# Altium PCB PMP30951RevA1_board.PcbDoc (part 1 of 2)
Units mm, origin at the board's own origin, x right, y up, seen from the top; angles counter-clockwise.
Board outline 87.63 x 58.42 mm, 2 copper layers (Top Layer, Bottom Layer), stack 1.575 mm thick; 82 components, 35 nets, 177 pads, 49 vias.
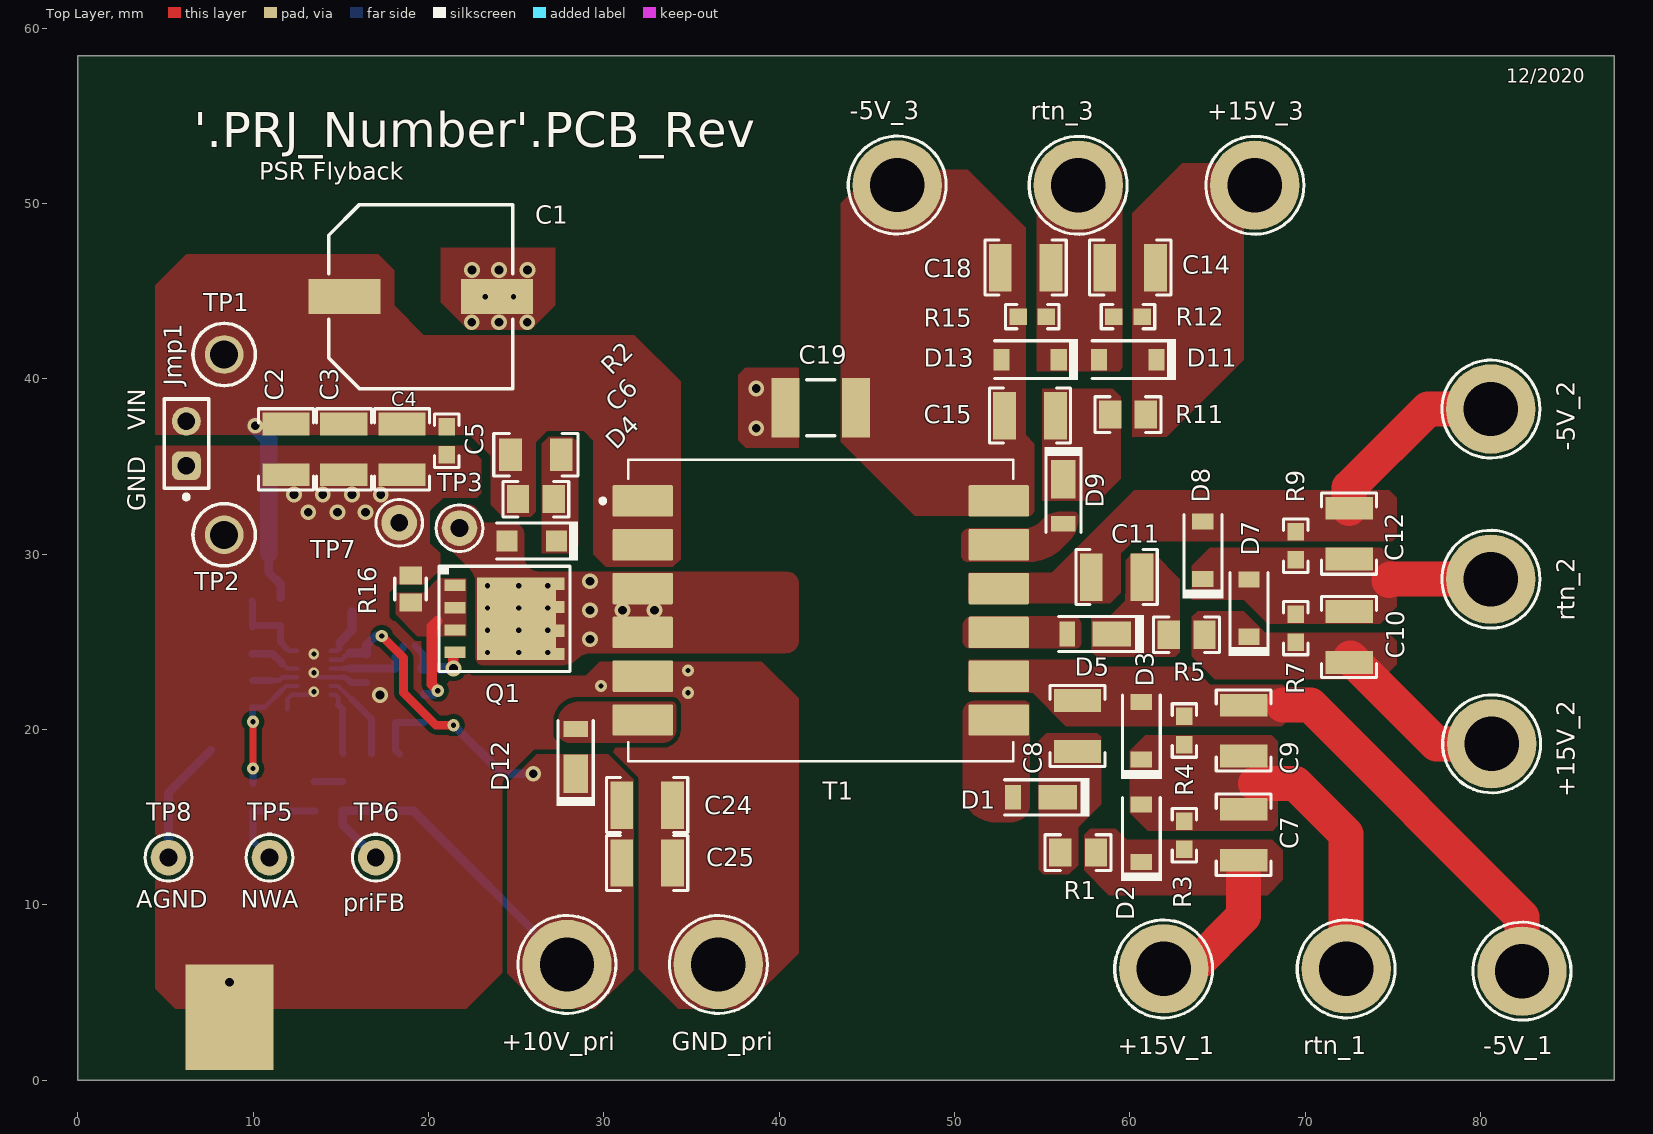
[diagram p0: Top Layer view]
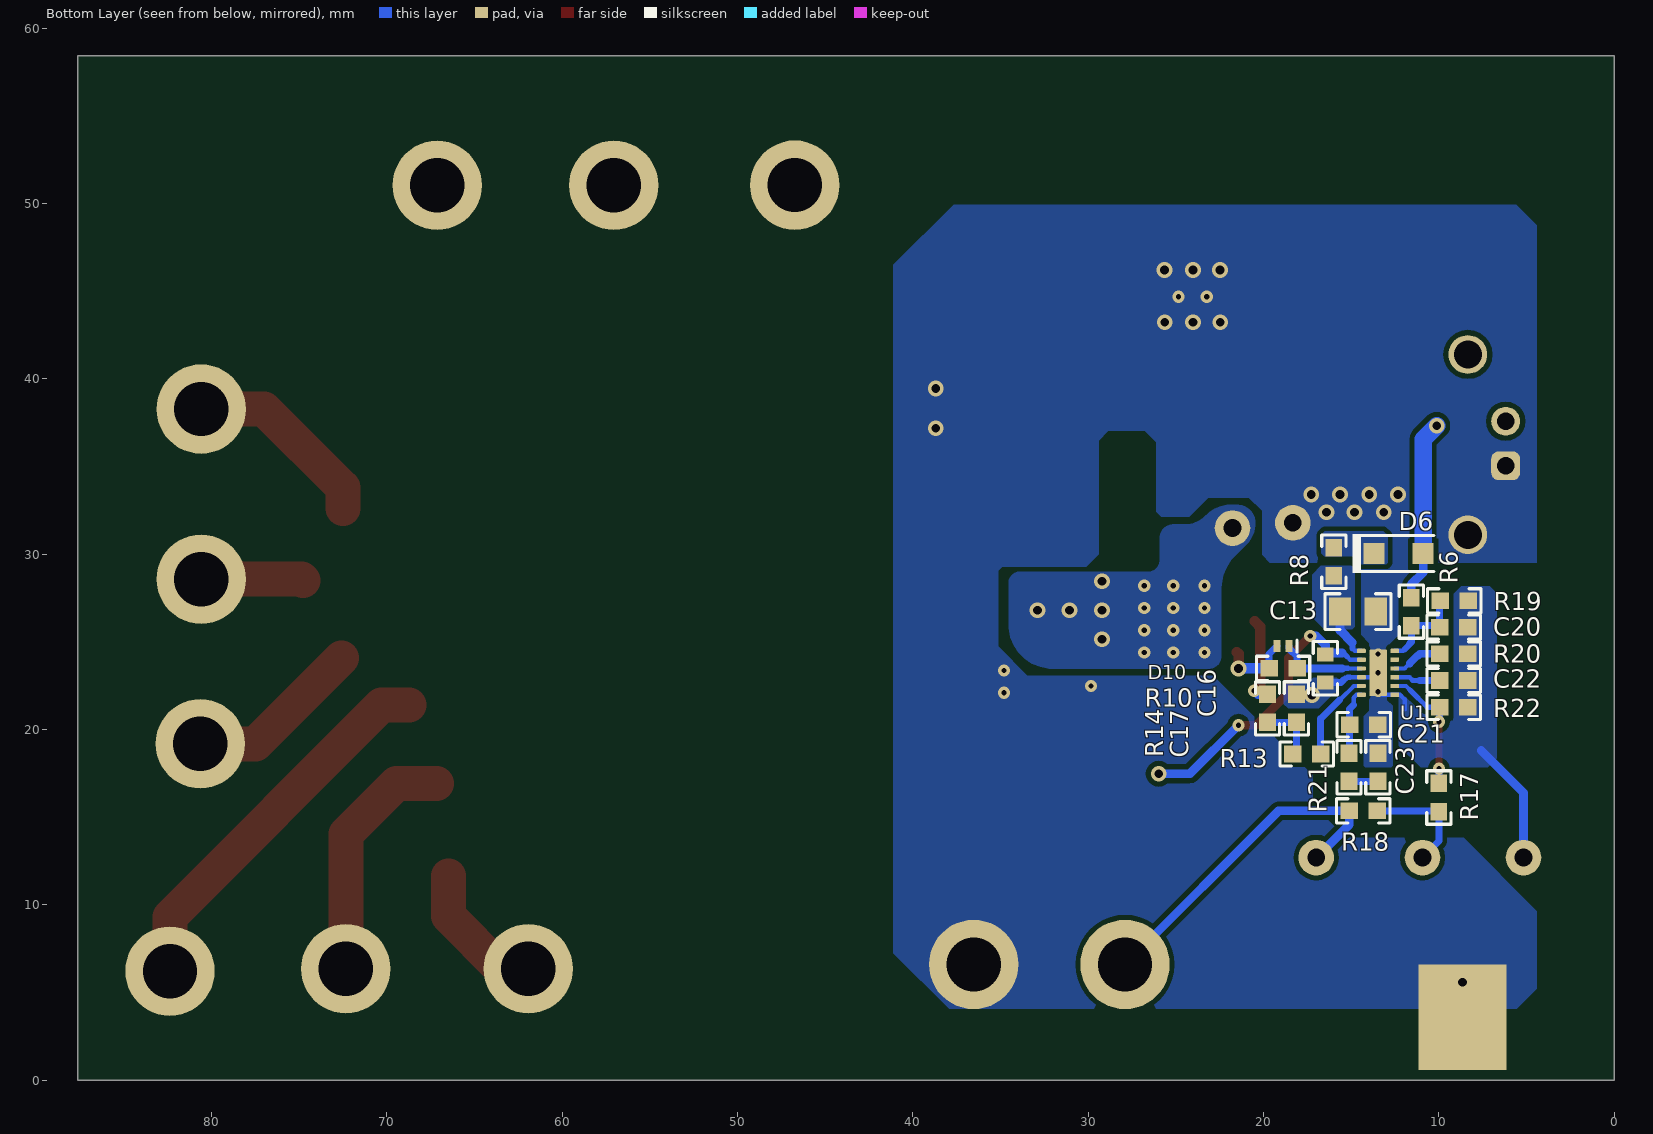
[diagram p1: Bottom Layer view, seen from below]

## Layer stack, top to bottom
Top Solder: solder mask 0.0102, Solder Resist, Dk 3.5
Top Layer: signal copper 0.0356
Dielectric1: core 1.5037, FR-4, Dk 4.8
Bottom Layer: signal copper 0.0356
Bottom Solder: solder mask 0.0102, Solder Resist, Dk 3.5

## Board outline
0,0 87.63,0 87.63,58.42 0,58.42

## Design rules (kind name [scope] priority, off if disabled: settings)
AcuteAngle [All] p1: minimum=4.50000000000000E+0001 checktracksonly=FALSE
AssemblyTestPointUsage [All] p1: valid=2
BoardOutlineClearance BoardOutlineClearance_MountingHoles [OnCopper and InComponentClass('Mounting Holes')] p1: gap=1 ignorepadtopadclearanceinfootprint=FALSE
BoardOutlineClearance BoardOutlineClearance_Poly [OnCopper and IsPoly] p2: gap=0.635 ignorepadtopadclearanceinfootprint=FALSE
BoardOutlineClearance [OnCopper and Not InComponentClass('Logo') and not InComponentClass('FiducialMark') and not InRegion(1000,500,4000,800) and not InPoly] p3: gap=1.905 ignorepadtopadclearanceinfootprint=FALSE
Clearance Clearance_Keepouts [((IsTrack Or IsArc) And Not InPoly) And IsFree and IsKeepOut vs ((IsTrack Or IsArc) And Not InPoly) And IsFree and IsKeepOut] p1: gap=0 ignorepadtopadclearanceinfootprint=FALSE
Clearance Clearance_Poly [InPolygon] p2: gap=0.28 ignorepadtopadclearanceinfootprint=TRUE
Clearance Clearance_FiducialMark [IsKeepOut and InComponentClass('FiducialMark') vs IsPad and InComponentClass('FiducialMark')] p3: gap=0 ignorepadtopadclearanceinfootprint=FALSE
Clearance [All] p4: gap=0.2 ignorepadtopadclearanceinfootprint=TRUE
ComponentClearance ComponentClearance_MountingHoles_FiducialMarks [InComponentClass('Mounting Holes') vs InComponentClass('FiducialMark')] p1: gap=1.27 collisioncheckmode=3 verticalgap=0.254 showdistances=FALSE
ComponentClearance ComponentClearance_Shunt [InComponentClass('Header') vs InComponentClass('Shunt')] p2: gap=0 collisioncheckmode=3 verticalgap=0 showdistances=FALSE
ComponentClearance ComponentClearance_Logo [InComponentClass('Logo')] p3: gap=1.27 collisioncheckmode=3 verticalgap=0.254 showdistances=FALSE
ComponentClearance ComponentClearance_ScrewToNut [(HasFootprint('NY PMS 440 0025 PH')) vs (HasFootprint('Keystone_1902C'))] p4: gap=0.127 collisioncheckmode=3 verticalgap=0.254 showdistances=FALSE
ComponentClearance ComponentClearance_MountingHoles [InComponentClass('Mounting Holes')] p5: gap=6.35 collisioncheckmode=3 verticalgap=2540 showdistances=FALSE
ComponentClearance ComponentClearance_SmallPassives [HasFootprint('0201*') or HasFootprint('0402*') or HasFootprint('0508') or HasFootprint('0603*') or HasFootprint('0612') or HasFootprint('0805*') or HasFootprint('0815*') or HasFootprint('0830*') or HasFootprint('1206*') or HasFootprint('1210*') or HasFootprint('1808*') or HasFootprint('1812*') or HasFootprint('1825*') or HasFootprint('2010*') or HasFootprint('2220*') or HasFootprint('2225*') or HasFootprint('2512*') or HasFootprint('2728*') or HasFootprint('3518*') or HasFootprint('X1-DFN1006-2') vs HasFootprint('0201*') or HasFootprint('0402*') or HasFootprint('0508') or HasFootprint('0603*') or HasFootprint('0612') or HasFootprint('0805*') or HasFootprint('0815*') or HasFootprint('0830*') or HasFootprint('1206*') or HasFootprint('1210*') or HasFootprint('1808*') or HasFootprint('1812*') or HasFootprint('1825*') or HasFootprint('2010*') or HasFootprint('2220*') or HasFootprint('2225*') or HasFootprint('2512*') or HasFootprint('2728*') or HasFootprint('3518*') or HasFootprint('X1-DFN1006-2')] p6: gap=0.38 collisioncheckmode=3 verticalgap=0.254 showdistances=FALSE
ComponentClearance ComponentClearance_THtoSMT [IsThruComponent vs IsSMTComponent] p7: gap=1.016 collisioncheckmode=3 verticalgap=0.762 showdistances=FALSE
ComponentClearance ComponentClearance_THtoTH [IsThruComponent vs IsThruComponent] p8: gap=0.762 collisioncheckmode=3 verticalgap=0.762 showdistances=FALSE
ComponentClearance [All] p9: gap=0.762 collisioncheckmode=3 verticalgap=0.254 showdistances=FALSE
DiffPairsRouting [All] p1: maxlimit=2.54 minlimit=0.254 mostfreqgap=0.254 toplayer_minwidth=0.381 toplayer_maxwidth=0.381 toplayer_prefwidth=0.381 bottomlayer_minwidth=0.381 bottomlayer_maxwidth=0.381 bottomlayer_prefwidth=0.381 maxuncoupledlength=25.4
FabricationTestPointUsage TestPointUsage [All] p1: valid=2 allowmultiple=FALSE
FabricationTestpoint Testpoint [All] p1: side=3 testpointundercomponent=TRUE minsize=1.016 maxsize=2.54 preferedsize=1.524 minholesize=0 maxholesize=1.016 preferedholesize=0.813 testpointgrid=0.025 allowsidetop=TRUE allowsidebottom=TRUE usegrid=TRUE gridtolerance=0
FanoutControl Fanout_LCC [IsLCC] p1: bgadir=Out bgaviamode=Centered fanoutstyle=Auto fanoutdirection=Alternating viagrid=0.025 // Fanout_LCC (Default Rule)
FanoutControl Fanout_BGA [IsBGA] p2: bgadir=Out bgaviamode=Centered fanoutstyle=Auto fanoutdirection=Alternating viagrid=0.025 // Fanout_BGA (Default Rule)
FanoutControl Fanout_Default [All] p4: bgadir=Out bgaviamode=Centered fanoutstyle=Auto fanoutdirection=Alternating viagrid=0.025 // Fanout_Default (Default Rule)
FanoutControl Fanout_Small [(CompPinCount < 5)] p5: bgadir=Out bgaviamode=Centered fanoutstyle=Auto fanoutdirection=OutThenIn viagrid=0.025 // Fanout_Small (Default Rule)
HoleSize [All] p1: absolutevalues=TRUE maxlimit=6.375 minlimit=0.3 maxpercent=80.000 minpercent=20.000
MinimumAnnularRing MinimumAnnularRing_ThermalPadVias [IsVia and InAnyComponent] p1: minimumring=0.15
MinimumAnnularRing [All] p2: minimumring=0.2
MinimumSolderMaskSliver MinimumSolderMaskSliver_Logo [InComponentClass('Logo') vs InComponentClass('Logo')] p1: minsoldermaskwidth=0.018
MinimumSolderMaskSliver [All] p2: minsoldermaskwidth=0.1
PlaneConnect [All] p1: planeconnectstyle=Relief reliefexpansion=0.254 reliefentries=4 reliefconductorwidth=0.254 reliefairgap=0.254
PolygonConnect PolygonConnect_TP8 [All vs InComponent('TP8')] p1: connectstyle=NoConnect reliefconductorwidth=0.254 reliefentries=4 polygonreliefangle="90 Angle" airgapwidth=0.254
PolygonConnect [All] p2: connectstyle=Direct reliefconductorwidth=0.254 reliefentries=4 polygonreliefangle="90 Angle" airgapwidth=0.254
RoutingVias ThermalPadVias [IsVia and InAnyComponent] p1: holewidth=0.2 width=0.5 viastyle="Through Hole" minholewidth=0.2 minwidth=0.5 maxholewidth=0.33 maxwidth=0.6
RoutingVias [All] p2: holewidth=0.5 width=0.9 viastyle="Through Hole" minholewidth=0.3 minwidth=0.6 maxholewidth=1.016 maxwidth=1.651
SilkToBoardRegionClearance [Not ((IsComment or IsDesignator) And (Hide <> 'False')) and not InRegion(1000,500,4000,800)] p1:
SilkToSilkClearance SilkToSilkClearance_Pb-FreeLogo [(HasFootprint('Pb-Free_Overlay_Medium') OR HasFootprint('Pb-Free_Overlay_Small')) vs (HasFootprint('Pb-Free_Overlay_Medium') OR HasFootprint('Pb-Free_Overlay_Small'))] p1: silktosilkclearance=0
SilkToSilkClearance [All] p2: silktosilkclearance=0.1
SilkToSolderMaskClearance SilkToComponentPadClearance [(IsPad or IsFill or IsRegion) and InAnycomponent] p1: minsilkscreentomaskgap=0.127 clearancetoexposedcopper=TRUE
SilkToSolderMaskClearance "Silk to Solder Mask Opening" [All] p2: minsilkscreentomaskgap=0.1 clearancetoexposedcopper=FALSE
SolderMaskExpansion [All] p1: expansion=0.05 istentingtop=FALSE
UnRoutedNet [All] p1: checkbadconnections=TRUE
Width [All] p1: maxlimit=2.54 minlimit=0.152 preferedwidth=0.254 checkconnectedcopper=TRUE
14 further rules are at their usual default settings.

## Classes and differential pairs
net class T1_Nets: GND Net-5V_1_1 Net-5V_2_1 Net-5V_3_1 NetD1_2 NetD5_2 NetD9_2 NetT?_7 NetT?_8 NetT?_9 NetT?_10 NetT?_11 NetT?_12 SW-aux SW_primary VIN
net class U1_Nets: 10Vaux GND NetC13_1 NetC20_1 NetC21_1 NetC22_1 NetD10_1 NetR13_1 NetR17_1 NetR20_2 NetU1_11
net class TP8_Nets: GND
net class TP7_Nets: GND
net class TP6_Nets: 10Vaux
net class TP5_Nets: NetR17_2
net class TP3_Nets: SW_primary
net class TP2_Nets: GND
net class TP1_Nets: VIN
net class rtn_3_Nets: NetC14_2
net class rtn_2_Nets: NetC10_2
net class rtn_1_Nets: NetC7_2
net class R22_Nets: GND NetR17_1
net class R21_Nets: NetC21_1 NetC23_1
net class R20_Nets: GND NetR20_2
net class R19_Nets: GND NetC20_1
net class R18_Nets: 10Vaux NetR17_2
net class R17_Nets: NetR17_1 NetR17_2
net class R16_Nets: GND NetQ1_1
net class R15_Nets: Net-5V_3_1 NetC14_2
net class R14_Nets: NetC17_1 NetQ1_1
net class R13_Nets: NetC17_1 NetR13_1
net class R12_Nets: Net+15V_3_1 NetC14_2
net class R11_Nets: Net+15V_3_1 NetC15_1
net class R10_Nets: NetD10_1 NetD10_2
net class R9_Nets: Net-5V_2_1 NetC10_2
net class R8_Nets: NetC13_1 NetD6_1
net class R7_Nets: Net+15V_2_1 NetC10_2
net class R6_Nets: NetC20_1 VIN
net class R5_Nets: Net+15V_2_1 NetC11_1
net class R4_Nets: Net-5V_1_1 NetC7_2
net class R3_Nets: Net+15V_1_1 NetC7_2
net class R2_Nets: NetC6_2 VIN
net class R1_Nets: Net+15V_1_1 NetC8_1
net class Q1_Nets: NetD10_2 NetQ1_1 SW_primary
net class Jmp1_Nets: GND VIN
net class GND_pri_Nets: GND
net class D13_Nets: Net-5V_3_1 NetC14_2
net class D12_Nets: 10Vaux NetD12_2 SW-aux
net class D11_Nets: Net+15V_3_1 NetC14_2
net class D10_Nets: NetD10_1 NetD10_2
net class D9_Nets: NetC15_1 NetD9_2
net class D8_Nets: Net-5V_2_1 NetC10_2
net class D7_Nets: Net+15V_2_1 NetC10_2
net class D6_Nets: NetD6_1 VIN
net class D5_Nets: NetC11_1 NetD5_2
net class D4_Nets: NetC6_2 SW_primary
net class D3_Nets: Net-5V_1_1 NetC7_2
net class D2_Nets: Net+15V_1_1 NetC7_2
net class D1_Nets: NetC8_1 NetD1_2
net class C25_Nets: 10Vaux GND
net class C24_Nets: 10Vaux GND
net class C23_Nets: GND NetC23_1
net class C22_Nets: GND NetC22_1
net class C21_Nets: GND NetC21_1
net class C20_Nets: GND NetC20_1
net class C19_Nets: GND Net-5V_3_1
net class C18_Nets: Net-5V_3_1 NetC14_2
net class C17_Nets: GND NetC17_1
net class C16_Nets: 10Vaux GND
net class C15_Nets: Net-5V_3_1 NetC15_1
net class C14_Nets: Net+15V_3_1 NetC14_2
net class C13_Nets: GND NetC13_1
net class C12_Nets: Net-5V_2_1 NetC10_2
net class C11_Nets: Net-5V_2_1 NetC11_1
net class C10_Nets: Net+15V_2_1 NetC10_2
net class C9_Nets: Net-5V_1_1 NetC7_2
net class C8_Nets: Net-5V_1_1 NetC8_1
net class C7_Nets: Net+15V_1_1 NetC7_2
net class C6_Nets: NetC6_2 VIN
net class C5_Nets: GND VIN
net class C4_Nets: GND VIN
net class C3_Nets: GND VIN
net class C2_Nets: GND VIN
net class C1_Nets: GND VIN
net class -5V_3_Nets: Net-5V_3_1
net class -5V_2_Nets: Net-5V_2_1
net class -5V_1_Nets: Net-5V_1_1
net class +15V_3_Nets: Net+15V_3_1
net class +15V_2_Nets: Net+15V_2_1
net class +15V_1_Nets: Net+15V_1_1
net class +10V_pri_Nets: 10Vaux
component class Header: Jmp1

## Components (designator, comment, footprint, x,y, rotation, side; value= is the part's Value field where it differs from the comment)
+10V_pri "Suggest using a net name here" Keystone1503-2 27.898,6.592 r0 top value=Double
+15V_1 "Suggest using a net name here" Keystone1503-2 61.934,6.338 r0 top value=Double
+15V_2 "Suggest using a net name here" Keystone1503-2 80.645,19.177 r0 top value=Double
+15V_3 "Suggest using a net name here" Keystone1503-2 67.141,51.042 r0 top value=Double
-5V_1 "Suggest using a net name here" Keystone1503-2 82.381,6.211 r0 top value=Double
-5V_2 "Suggest using a net name here" Keystone1503-2 80.603,38.276 r0 top value=Double
-5V_3 "Suggest using a net name here" Keystone1503-2 46.736,51.054 r0 top value=Double
C1 "EEH-ZC1H101P" Panasonic_G 19.561,44.692 r0 top value=100uF
C2 "GRM32ER71H106KA12L" 1210_270 11.871,35.976 r270 top value=10uF
C3 "GRM32ER71H106KA12L" 1210_270 15.171,35.976 r270 top value=10uF
C4 "GRM32ER71H106KA12L" 1210_270 18.483,35.976 r270 top value=10uF
C5 "GCM188R71H104KA57D" 0603#1 21.04,36.476 r270 top value=0.1uF
C6 "GRM21BR72A103MA01L" 0805_HV 26.12,33.135 r0 top value=0.01uF
C7 "GRM32ER71E226KE15L" 1210_270 66.502,13.992 r90 top value=22uF
C8 "GRM32ER71H106KA12L" 1210_270 57.023,20.193 r90 top value=10uF
C9 "GRM32ER71E226KE15L" 1210_270 66.502,19.935 r90 top value=22uF
C10 "GRM32ER71E226KE15L" 1210_270 72.517,25.273 r90 top value=22uF
C11 "GRM32ER71H106KA12L" 1210_270 59.252,28.69 r180 top value=10uF
C12 "GRM32ER71E226KE15L" 1210_270 72.517,31.168 r90 top value=22uF
C13 "GRM21BR71H105KA12L" 0805_HV 14.612,26.725 r180 bottom value=1uF
C14 "GRM32ER71E226KE15L" 1210_270 60.029,46.343 r180 top value=22uF
C15 "GRM32ER71H106KA12L" 1210_270 54.314,37.901 r180 top value=10uF
C16 "GRM188R71C105KA12D" 0603#2 16.468,23.483 r270 bottom value=1uF
C17 "GRM188R71E102KA01D" 0603#1 18.119,21.197 r90 bottom value=1000pF
C18 "GRM32ER71E226KE15L" 1210_270 54.06,46.343 r180 top value=22uF
C19 "HV1812Y102KXVATHV" 1812_280 42.376,38.342 r180 top value=1000pF
C20 "GRM1885C1H100JA01D" 0603#1 9.151,25.836 r180 bottom value=10pF
C21 "GRM1885C1H151JA01D" 0603#1 14.281,20.269 r180 bottom value=150pF
C22 "GRM188R71E104KA01D" 0603#1 9.151,22.788 r180 bottom value=0.1uF
C23 "GRM188R71E333KA01D" 0603#1 13.469,17.835 r90 bottom value=0.033uF
C24 "GRM32ER71E226KE15L" 1210_270 32.47,15.68 r0 top value=22uF
C25 "GRM32ER71E226KE15L" 1210_270 32.47,12.378 r0 top value=22uF
D1 "DFLS1200-7" PowerDI123 54.61,16.129 r180 top value=200V
D2 "MMSZ5245B-7-F" SOD-123 60.664,14.085 r90 top value=15V
D3 "MMSZ5231B-7-F" SOD-123 60.664,19.927 r90 top value=5.1V
D4 "BAT46WH,115" SOD-123F 25.887,30.749 r180 top value=100V
D5 "DFLS1200-7" PowerDI123 57.707,25.444 r180 top value=200V
D6 "BAT46WH,115" SOD-123F 12.289,30.036 r180 bottom value=100V
D7 "MMSZ5245B-7-F" SOD-123 66.802,26.924 r90 top value=15V
D8 "MMSZ5231B-7-F" SOD-123 64.177,30.214 r90 top value=5.1V
D9 "DFLS1200-7" PowerDI123 56.219,33.008 r270 top value=200V
D10 "BAT54LP-7" X1-DFN1006-2 18.881,24.753 r0 bottom value=30V
D11 "MMSZ5245B-7-F" SOD-123 59.887,41.092 r180 top value=15V
D12 "DFLS1100-7" PowerDI123 28.395,18.743 r90 top value=100V
D13 "MMSZ5231B-7-F" SOD-123 54.314,41.092 r180 top value=5.1V
GND_pri "Suggest using a net name here" Keystone1503-2 36.534,6.592 r0 top value=Double
Jmp1 "TSW-102-07-G-S" TSW-102-07-G-S 6.181,36.31 r90 top
Q1 "BSC340N08NS3 G" PG-TDSON-8 24.34,26.309 r0 top value=80V
R1 "CRCW080510R0FKEA" 0805_HV 57.057,12.976 r0 top value=10.0
R2 "CRCW1206100KJNEA" 1206 26.12,35.675 r180 top value=100k
R3 "CRCW060315K0FKEA" 0603#1 63.119,13.97 r270 top value=15.0k
R4 "CRCW06035K11FKEA" 0603#1 63.119,19.939 r270 top value=5.11k
R5 "CRCW080510R0FKEA" 0805_HV 63.246,25.4 r0 top value=10.0
R6 "CRCW0603332KFKEA" 0603#1 11.564,26.725 r90 bottom value=332k
R7 "CRCW060315K0FKEA" 0603#1 69.469,25.781 r270 top value=15.0k
R8 "CRCW060310R0FKEA" 0603#1 15.983,29.561 r90 bottom value=10.0
R9 "CRCW06035K11FKEA" 0603#1 69.469,30.48 r270 top value=5.11k
R10 "CRCW060310R0FKEA" 0603#1 18.881,23.483 r0 bottom value=10.0
R11 "CRCW08054R64FKEA" 0805_HV 59.902,37.961 r0 top value=4.64
R12 "CRCW060315K0FKEA" 0603#1 59.902,43.549 r0 top value=15.0k
R13 "CRCW06030000Z0EA" 0603#1 17.533,18.597 r0 bottom value=0
R14 "CRCW0603100RFKEA" 0603#1 19.77,21.197 r90 bottom value=100
R15 "CRCW06035K11FKEA" 0603#1 54.441,43.549 r0 top value=5.11k
R16 "WSL0805R0100FEA18" WSLHP0805 18.983,28.011 r270 top value=0.01
R17 "CRCW060310K0FKEA" 0603#1 9.991,16.117 r270 bottom value=10.0k
R18 "CRCW060349R9FKEA" 0603#1 14.309,15.355 r0 bottom value=49.9
R19 "CRCW0603100KFKEA" 0603#1 9.125,27.334 r0 bottom value=100k
R20 "CRCW0603110KFKEA" 0603#1 9.151,24.312 r0 bottom value=110k
R21 "CRCW060310K0FKEA" 0603#1 15.12,17.835 r90 bottom value=10.0k
R22 "CRCW06031K10FKEA" 0603#1 9.151,21.264 r0 bottom value=1.10k
rtn_1 "Suggest using a net name here" Keystone1503-2 72.348,6.338 r0 top value=Double
rtn_2 "Suggest using a net name here" Keystone1503-2 80.603,28.572 r0 top value=Double
rtn_3 "Suggest using a net name here" Keystone1503-2 57.057,51.042 r0 top value=Double
T1 "ZB1465-AL" FP-ZB1465-AL_SMT_XFRMR_21MM97_17MM20-MFG 42.376,26.785 r0 top
TP1 "5010" Keystone5010 8.34,41.39 r90 top
TP2 "5011" Keystone5011 8.34,31.103 r90 top
TP3 "5002" Keystone5002 21.765,31.484 r90 top
TP5 "5003" Keystone5003 10.929,12.688 r90 top
TP6 "5000" Keystone5000 16.992,12.688 r90 top value=Red
TP7 "5001" Keystone5001 18.326,31.786 r90 top value=Black
TP8 "5001" Keystone5001 5.165,12.688 r90 top value=Black
U1 "LM51551QDSSTQ1" DSS0012C 13.462,23.228 r180 bottom

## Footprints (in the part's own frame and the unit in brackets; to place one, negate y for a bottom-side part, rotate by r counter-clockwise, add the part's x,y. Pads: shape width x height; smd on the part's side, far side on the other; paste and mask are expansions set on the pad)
0603#1 [mm] "0603 from SM-752 data"
  rect 1x0.95 smd: 1(-0.8,0) 2(0.8,0)
  silkscreen extent -1.52,-0.69 1.52,0.69, body extent -0.87,-0.47 0.87,0.47, height 1
0603#2 [mm] "0603 from SM-752 data"
  rect 0.8x0.95 smd: 1(-0.8,0) 2(0.8,0)
  silkscreen extent -1.52,-0.69 1.52,0.69, body extent -0.87,-0.47 0.87,0.47, height 1
0805_HV [mil] "0805 with 30mil clearance between pads"
  rect 50x63 smd: 1(-40,0) 2(40,0)
  silkscreen extent -74,-40 74,40, body extent -43,-29 43,29, height 57
1206 [mm] "1206 from SM-752 data"
  rect 1.3x1.85 smd: 1(-1.45,0) 2(1.45,0)
  silkscreen extent -2.4,-1.21 2.4,1.21, body extent -1.7,-0.9 1.7,0.9, height 1.35
1210_270 [mm] "1210"
  rect 1.3x2.7 smd: 1(-1.45,0) 2(1.45,0)
  silkscreen extent -2.32,-1.57 2.32,1.57, body extent -1.7,-1.35 1.7,1.35, height 2.7
1812_280 [mm] "1812"
  rect 1.6x3.4 smd: 1(-2,0) 2(2,0)
  silkscreen extent -0.8,-1.6 0.8,1.6, body extent -2.4,-1.7 2.4,1.7, height 2.8
DSS0012C [mm] "WSON-12"
  rrect40% 0.5x0.25 smd: 1(-0.95,1.25) 2(-0.95,0.75) 3(-0.95,0.25) 4(-0.95,-0.25) 5(-0.95,-0.75) 6(-0.95,-1.25) 7(0.95,-1.25) 8(0.95,-0.75) 9(0.95,-0.25) 10(0.95,0.25) 11(0.95,0.75) 12(0.95,1.25)
  rrect11% 0.95x1.17 on Bottom Paste: 13(0,-0.685) 13(0,0.685)
  rrect11% 1x2.65 smd paste-0.5: 13(0,0)
  body extent -1,-1.5 1,1.5, height 0.81
FP-ZB1465-AL_SMT_XFRMR_21MM97_17MM20-MFG [mm]
  rrect6% 3.43x1.79 smd paste+0 mask+0: 1(-10.155,6.25) 2(-10.155,3.75) 3(-10.155,1.25) 4(-10.155,-1.25) 5(-10.155,-3.75) 6(-10.155,-6.25) 7(10.155,-6.25) 8(10.155,-3.75) 9(10.155,-1.25) 10(10.155,1.25) 11(10.155,3.75) 12(10.155,6.25)
  silkscreen extent -12.56,-8.6 10.98,8.6, body extent -11.97,-8.7 11.97,8.7, height 0.25
Keystone1503-2 [mm] "Double Turret"
  round 5.1 hole 3.1: 1(0,0)
  silkscreen extent -2.79,-2.79 2.79,2.79, body extent -2.4,-2.4 2.38,2.4, height 9.22
Keystone5000 [mil] "For Keystone 500x miniature loop terminals"
  round 80 hole 40: 1(0,0)
  silkscreen extent -52,-52 52,52, body extent -49,-49 49,49, height 182
Keystone5001 [mil] "For Keystone 500x miniature loop terminals"
  round 80 hole 40: 1(0,0)
  silkscreen extent -52,-52 52,52, body extent -49,-49 49,49, height 182
Keystone5002 [mil] "For Keystone 500x miniature loop terminals"
  round 80 hole 40: 1(0,0)
  silkscreen extent -52,-52 52,52, body extent -49,-49 49,49, height 182
Keystone5003 [mil] "For Keystone 500x miniature loop terminals"
  round 80 hole 40: 1(0,0)
  silkscreen extent -52,-52 52,52, body extent -49,-49 49,49, height 182
Keystone5010 [mil] "Keystone Multipurpose loops"
  round 87 hole 63: 1(0,0)
  silkscreen extent -70,-70 70,70, body extent -63,-63 63,62, height 319
Keystone5011 [mil] "Keystone Multipurpose loops"
  round 87 hole 63: 1(0,0)
  silkscreen extent -70,-70 70,70, body extent -63,-63 63,62, height 319
Panasonic_G [mm] "SMD, 2-Leads, Dia 10mm"
  rect 4.1x2 smd: 1(-4.35,0) 2(4.35,0)
  silkscreen extent -5.25,-5.25 5.25,5.25, body extent -5.25,-5.25 5.25,5.25, height 10.51
PG-TDSON-8 [mm] "Infineon recommended land pattern"
  rect 1.2x0.65 smd: 1(-2.825,1.905) 2(-2.825,0.635) 3(-2.825,-0.635) 4(-2.825,-1.905)
  rect 0.5x0.7 smd: 5(3.175,-2) 6(3.175,-0.675) 7(3.175,0.675) 8(3.175,2)
  rect 4.5x4.7 smd paste-2.25: 9(0.675,0)
  silkscreen extent -3.74,-3 3.74,3, body extent -3.17,-2.89 3.17,2.9, height 1.1
PowerDI123 [mm] "Diodes Inc recommended land pattern, document number DS30628 Rev. 6-2"
  rect 2.2x1.4 smd: 1(-1.275,0)
  rect 0.9x1.4 smd: 2(1.275,0)
  silkscreen extent -3.1,-1.09 1.76,1.09, body extent -2.38,-0.97 1.52,0.96, height 1
SOD-123 [mm] "On Semi recommended land pattern"
  rect 0.915x1.22 smd: 1(-1.637,0) 2(1.637,0)
  silkscreen extent -2.74,-1.17 2.03,1.17, body extent -1.93,-0.9 1.93,0.9, height 1.35
SOD-123F [mm] "NXP recommended land pattern"
  rect 1.2x1.2 smd paste-0.05: 1(-1.4,0) 2(1.4,0)
  silkscreen extent -2.64,-1.12 2.01,1.12, body extent -1.8,-0.85 1.8,0.85, height 1.2
TSW-102-07-G-S [mm] "Samtec 100mil, 1x2, 230 mil above insulator"
  rrect50% 1.65x1.65 hole 1.016: 1(-1.27,0)
  round 1.65 hole 1.016: 2(1.27,0)
  silkscreen extent -3.17,-1.27 2.54,1.27, body extent -2.54,-1.27 2.54,1.27, height 8.38
WSLHP0805 [mm] "Vishay"
  rect 1.02x1.27 smd: 1(-0.76,0) 2(0.76,0)
  silkscreen extent -0.6,-0.9 0.6,0.9, body extent -1.14,-0.76 1.14,0.76, height 0.51
X1-DFN1006-2 [mm] "DIODES, INC"
  rect 0.4x0.7 smd: 1(-0.35,0) 2(0.35,0)
  silkscreen extent -0.8,-0.35 -0.8,0.35, body extent -0.54,-0.34 0.54,0.34, height 0.53

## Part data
+10V_pri +15V_1 +15V_2 +15V_3 -5V_1 -5V_2 -5V_3 GND_pri rtn_1 rtn_2 rtn_3: library part 1503-2, "Terminal, Turret, TH, Double", Manufacturer=Keystone, Supplier Part Number 1=36-1503-2-ND
C1: "CAP, Polymer Hybrid, 100 µF, 50 V,+/- 20%, 0.028 ohm, AEC-Q200 Grade 1, D10xL10.2mm SMD", Cap_Case=10x10.2mm, Manufacturer=Panasonic, Supplier Part Number 1=P15462CT-ND, Tolerance_%=20, Value1="0.028 ohm", Value2=50V, ValueDisplayed=100µF
C2 C3 C4 C8 C11 C15: library part CMP-0009226-3, "CAP, CERM, 10 uF, 50 V, +/- 10%, X7R, 1210", Cap_Case=1210, Manufacturer=MuRata, Supplier Part Number 1=490-6544-1-ND, TempCo=X7R, Tolerance_%=10%, Value1=Unknown, Value2=50V, ValueDisplayed=10uF
C5: "CAP, CERM, 0.1 µF, 50 V, +/- 10%, X7R, 0603", Cap_Case=0603, Manufacturer=MuRata, Supplier Part Number 1=490-4779-1-ND, TempCo=X7R, Tolerance_%=10, Value1="0.02 ohm", Value2=50V, ValueDisplayed=0.1µF
C6: "CAP, CERM, 0.01 µF, 100 V, +/- 20%, X7R, 0805", Cap_Case=0805, Manufacturer=MuRata, Supplier Part Number 1=490-1653-1-ND, TempCo=X7R, Tolerance_%=20, Value1=Unknown, Value2=100V, ValueDisplayed=0.01µF
C7 C9 C10 C12 C14 C18 C24 C25: library part CMP-0009224-2, "CAP, CERM, 22 uF, 25 V, +/- 10%, X7R, 1210", Cap_Case=1210, Manufacturer=MuRata, Supplier Part Number 1=490-5313-1-ND, TempCo=X7R, Tolerance_%=10%, Value1=Unknown, Value2=25V, ValueDisplayed=22uF
C13: "CAP, CERM, 1 µF, 50 V,+/- 10%, X7R, 0805", Cap_Case=0805, Manufacturer=MuRata, Supplier Part Number 1=490-4736-1-ND, TempCo=X7R, Tolerance_%=10, Value2=50V, ValueDisplayed=1µF
C16: "CAP, CERM, 1 µF, 16 V, +/- 10%, X7R, 0603", Cap_Case=0603, Manufacturer=MuRata, Supplier Part Number 1=490-3900-1-ND, TempCo=X7R, Tolerance_%=10, Value1="0.011 ohm", Value2=16V, ValueDisplayed=1µF
C17: "CAP, CERM, 1000 pF, 25 V,+/- 10%, X7R, 0603", Cap_Case=0603, Manufacturer=MuRata, Supplier Part Number 1=GRM188R71E102KA01D-ND, TempCo=X7R, Tolerance_%=10, Value2=25V, ValueDisplayed=1000pF
C19: "CAP, CERM, 1000 pF, 4000 V,+/- 10%, X7R, 1812", Cap_Case=1812, Manufacturer=Vishay-Vitramon, Supplier Part Number 1=720-1549-1-ND, TempCo=X7R, Tolerance_%=10, Value2=4000V, ValueDisplayed=1000pF
C20: "CAP, CERM, 10 pF, 50 V,+/- 5%, C0G/NP0, 0603", Cap_Case=0603, Manufacturer=MuRata, Supplier Part Number 1=490-1403-1-ND, TempCo=C0G/NP0, Tolerance_%=5, Value2=50V, ValueDisplayed=10pF
C21: "CAP, CERM, 150 pF, 50 V,+/- 5%, C0G/NP0, 0603", Cap_Case=0603, Manufacturer=MuRata, Supplier Part Number 1=490-1431-1-ND, TempCo=C0G/NP0, Tolerance_%=5, Value2=50V, ValueDisplayed=150pF
C22: "CAP, CERM, 0.1 µF, 25 V,+/- 10%, X7R, 0603", Cap_Case=0603, Manufacturer=MuRata, Supplier Part Number 1=490-1524-1-ND, TempCo=X7R, Tolerance_%=10, Value2=25V, ValueDisplayed=0.1µF
C23: "CAP, CERM, 0.033 µF, 25 V,+/- 10%, X7R, 0603", Cap_Case=0603, Manufacturer=MuRata, Supplier Part Number 1=490-1521-1-ND, TempCo=X7R, Tolerance_%=10, Value2=25V, ValueDisplayed=0.033µF
D1 D5 D9: "Diode, Schottky, 200 V, 1 A, PowerDI123", Manufacturer="Diodes Inc.", Supplier Part Number 1=DFLS1200DICT-ND, Value1=1A, Value2=0.85V
D2 D7 D11: "Diode, Zener, 15 V, 500 mW, SOD-123", Manufacturer="Diodes Inc.", Power_W=0.5, Supplier Part Number 1=MMSZ5245B-FDICT-ND, Value1=0.5W
D3 D8 D13: "Diode, Zener, 5.1 V, 500 mW, SOD-123", Manufacturer="Diodes Inc.", Power_W=0.5, Supplier Part Number 1=MMSZ5231B-FDICT-ND, Value1=0.5W
D4 D6: "Diode, Schottky, 100 V, 0.25 A, SOD-123F", Manufacturer=Nexperia, Supplier Part Number 1=568-6016-1-ND, Value1=0.25A, Value2=0.85V
D10: "Diode, Schottky, 30 V, 0.2 A, 1.00x0.50x0.60mm", Manufacturer="Diodes Inc.", Supplier Part Number 1=BAT54LPDICT-ND, Value1=0.2A, Value2=1V
D12: "Diode, Schottky, 100 V, 1 A, PowerDI123", Manufacturer="Diodes Inc.", Supplier Part Number 1=DFLS1100DICT-ND, Value1=1A, Value2=0.77V
Jmp1: library part CMP-0075405-3, "Header, 100mil, 2x1, Gold, TH", Color=Black, Current_A=6.3A, Manufacturer=Samtec, Supplier Part Number 1=SAM1029-02-ND, Voltage_V=550V
Q1: "MOSFET, N-CH, 80 V, 23 A, PG-TDSON-8", Alternate Manufacturer=None, Manufacturer="Infineon Technologies", Supplier Part Number 1="BSC340N08NS3 GCT-ND", Value1="0.065 ohm", Value2="6.8 nC"
R1 R5: "RES, 10.0, 1%, 0.125 W, 0805", Manufacturer=Vishay-Dale, Power_W=0.125, Supplier Part Number 1=541-10.0CCT-ND, TempCo="100 ppm/C", Tolerance_%=1, Value1=1%, Value2=0.125W, Value_Code=10R0, ValueDisplayed=10.0
R2: "RES, 100 k, 5%, 0.25 W, 1206", Manufacturer=Vishay-Dale, Power_W=0.25, Supplier Part Number 1=541-100KECT-ND, TempCo="200 ppm/C", Tolerance_%=5, Value1=5%, Value2=0.25W, Value_Code=100k
R3 R7 R12: "RES, 15.0 k, 1%, 0.1 W, 0603", Manufacturer=Vishay-Dale, Power_W=0.1, Supplier Part Number 1=541-15.0KHCT-ND, TempCo="100 ppm/C", Tolerance_%=1, Value1=1%, Value2=0.1W, Value_Code=15k0, ValueDisplayed=15.0k
R4 R9 R15: "RES, 5.11 k, 1%, 0.1 W, 0603", Manufacturer=Vishay-Dale, Power_W=0.1, Supplier Part Number 1=541-5.11KHCT-ND, TempCo="100 ppm/C", Tolerance_%=1, Value1=1%, Value2=0.1W, Value_Code=5k11, ValueDisplayed=5.11k
R6: "RES, 332 k, 1%, 0.1 W, 0603", Manufacturer=Vishay-Dale, Power_W=0.1, Supplier Part Number 1=541-332KHCT-ND, TempCo="100 ppm/C", Tolerance_%=1, Value1=1%, Value2=0.1W, Value_Code=332k
R8 R10: "RES, 10.0, 1%, 0.1 W, 0603", Manufacturer=Vishay-Dale, Power_W=0.1, Supplier Part Number 1=541-10.0HCT-ND, TempCo="100 ppm/C", Tolerance_%=1, Value1=1%, Value2=0.1W, Value_Code=10R0, ValueDisplayed=10.0
R11: "RES, 4.64, 1%, 0.125 W, 0805", Manufacturer=Vishay-Dale, Power_W=0.125, Supplier Part Number 1=541-4.64CCCT-ND, TempCo="100 ppm/C", Tolerance_%=1, Value1=1%, Value2=0.125W, Value_Code=4R64, ValueDisplayed=4.64
R13: "RES, 0, 5%, 0.1 W, 0603", Manufacturer=Vishay-Dale, Power_W=0.1, Supplier Part Number 1=541-0.0GCT-ND, TempCo="200 ppm/C", Tolerance_%=5, Value1=5%, Value2=0.1W, Value_Code=0000, ValueDisplayed=0
R14: "RES, 100, 1%, 0.1 W, 0603", Manufacturer=Vishay-Dale, Power_W=0.1, Supplier Part Number 1=541-100HCT-ND, TempCo="100 ppm/C", Tolerance_%=1, Value1=1%, Value2=0.1W, Value_Code=100R, ValueDisplayed=100
R16: "RES, 0.01, 1%, 0.25 W, AEC-Q200 Grade 0, 0805", Manufacturer=Vishay-Dale, Power_W=0.25, Supplier Part Number 1=WSLB-.01DKR-ND, TempCo="75 ppm/C", Tolerance_%=1, Value1=1%, Value2=0.25W, Value_Code=R010, ValueDisplayed=0.01
R17 R21: "RES, 10.0 k, 1%, 0.1 W, 0603", Manufacturer=Vishay-Dale, Power_W=0.1, Supplier Part Number 1=541-10.0KHCT-ND, TempCo="100 ppm/C", Tolerance_%=1, Value1=1%, Value2=0.1W, Value_Code=10k0, ValueDisplayed=10.0k
R18: "RES, 49.9, 1%, 0.1 W, 0603", Manufacturer=Vishay-Dale, Power_W=0.1, Supplier Part Number 1=541-49.9HCT-ND, TempCo="100 ppm/C", Tolerance_%=1, Value1=1%, Value2=0.1W, Value_Code=49R9, ValueDisplayed=49.9
R19: "RES, 100 k, 1%, 0.1 W, 0603", Manufacturer=Vishay-Dale, Power_W=0.1, Supplier Part Number 1=541-100KHCT-ND, TempCo="100 ppm/C", Tolerance_%=1, Value1=1%, Value2=0.1W, Value_Code=100k
R20: "RES, 110 k, 1%, 0.1 W, 0603", Manufacturer=Vishay-Dale, Power_W=0.1, Supplier Part Number 1=541-110KHCT-ND, TempCo="100 ppm/C", Tolerance_%=1, Value1=1%, Value2=0.1W, Value_Code=110k
R22: "RES, 1.10 k, 1%, 0.1 W, 0603", Manufacturer=Vishay-Dale, Power_W=0.1, Supplier Part Number 1=541-1.10KHCT-ND, TempCo="100 ppm/C", Tolerance_%=1, Value1=1%, Value2=0.1W, Value_Code=1k10, ValueDisplayed=1.10k
T1: library part CMP-0091454-1, "Flyback Transformer, 1.62uH, 1:1.5:3:3:3, VISO 3kVrms, 21.97x17.2x8.64mm", Manufacturer=Coilcraft, Operating Temperature Range=to, Voltage_Isolation_Vrms=3000Vrms
TP1: library part CMP-0055147-1, "Test Point, Multipurpose, Red, TH", Color=Red, Manufacturer=Keystone, Supplier Part Number 1=36-5010-ND
TP2: library part CMP-0055148-1, "Test Point, Multipurpose, Black, TH", Color=Black, Manufacturer=Keystone, Supplier Part Number 1=36-5011-ND
TP3: "Test Point, Miniature, White, TH", Color=White, Manufacturer=Keystone, Supplier Part Number 1=36-5002-ND
TP5: "Test Point, Miniature, Orange, TH", Color=Orange, Manufacturer=Keystone, Supplier Part Number 1=36-5003-ND
TP6: "Test Point, Miniature, Red, TH", Manufacturer=Keystone, Supplier Part Number 1=5000K-ND
TP7 TP8: "Test Point, Miniature, Black, TH", Manufacturer=Keystone, Supplier Part Number 1=5001K-ND
U1: library part CMP-0081540-1, "Automotive Grade 2.2-MHz Wide Input Non-synchronous Boost Controller, DSS0012C (WSON-12)", Alternate Manufacturer="Texas Instruments", Alternate PartNumber=LM51551QDSSRQ1

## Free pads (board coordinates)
  rect 5x6 hole 0.5 copper offset 0,-2: 17(8.65,5.576)

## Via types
v1: diameter 0.9, hole 0.5, Top Layer to Bottom Layer, tented top, 19 vias
v2: diameter 0.7, hole 0.3, Top Layer to Bottom Layer, 16 vias
v3: diameter 0.9, hole 0.5, Top Layer to Bottom Layer, 4 vias
v4: diameter 0.7, hole 0.3, Top Layer to Bottom Layer, tented top, 3 vias
v5: diameter 0.7, hole 0.3, Top Layer to Bottom Layer, tented bottom, 3 vias
v6: diameter 0.6, hole 0.3, Top Layer to Bottom Layer, 3 vias
v7: diameter 0.9, hole 0.5, Top Layer to Bottom Layer, tented bottom, 1 vias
